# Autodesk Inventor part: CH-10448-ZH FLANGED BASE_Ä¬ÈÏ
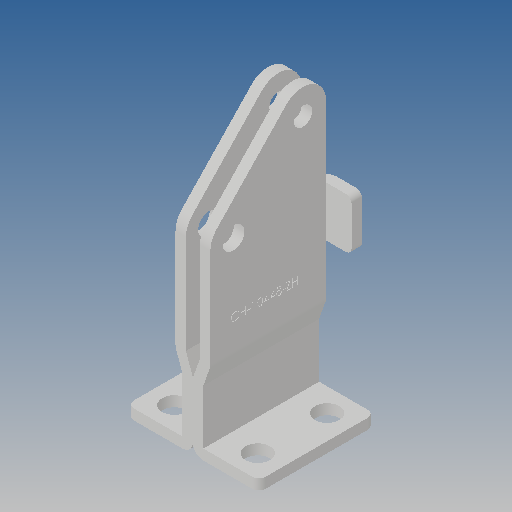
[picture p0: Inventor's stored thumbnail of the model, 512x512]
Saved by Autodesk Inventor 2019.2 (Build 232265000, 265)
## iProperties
Created: 2010-06
Part Number: CH-10448-ZH FLANGED BASE_Ä¬ÈÏ
Material: Ogólny
Document SubType Name: Modeling
Designer: CADENGINEERING4
Density: 1 g/cm^3
Appearance: Domyślna
Author: CADENGINEERING4
Revision Number: ÈÎºÎ
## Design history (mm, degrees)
feature "NONE"
feature "NONE:1"
node "Bryła1"
node "Bryła2"
